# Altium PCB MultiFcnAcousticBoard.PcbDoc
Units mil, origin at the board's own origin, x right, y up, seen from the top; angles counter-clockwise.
Board outline 6000 x 4000 mil, 2 copper layers (Top Layer, Bottom Layer); 88 components, 62 nets, 279 pads, 39 vias.
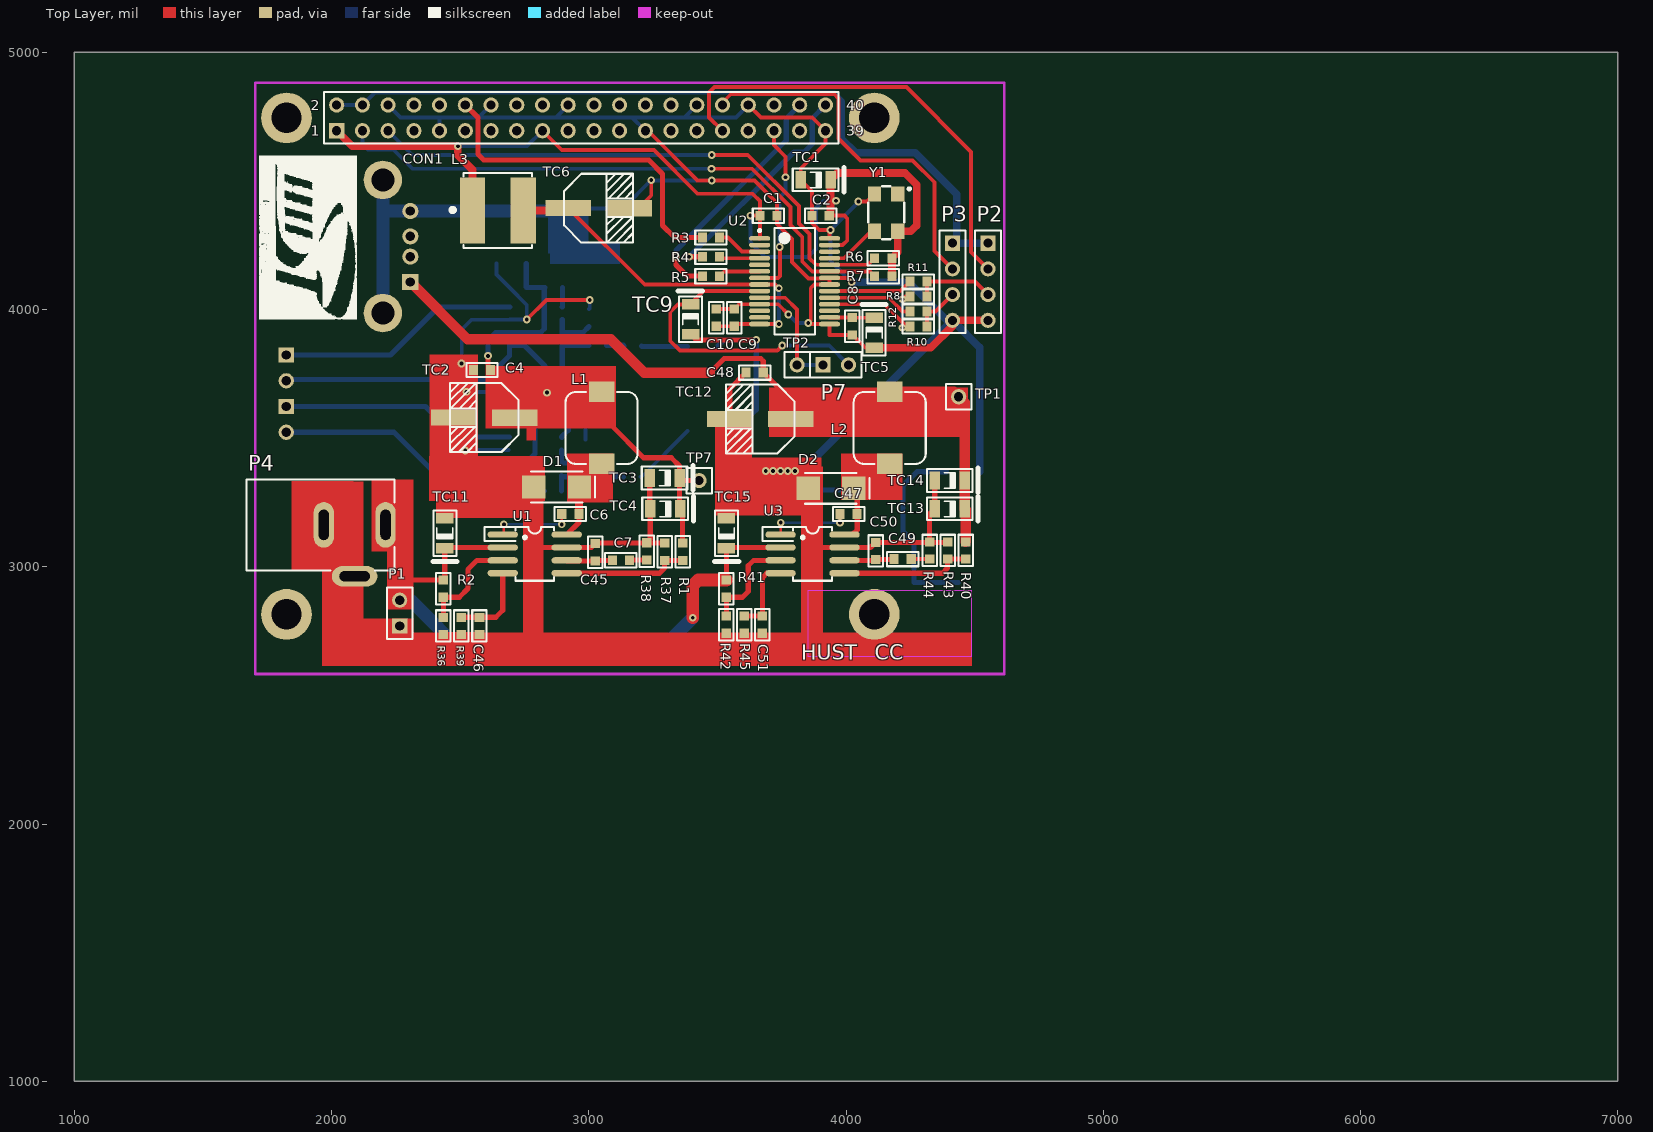
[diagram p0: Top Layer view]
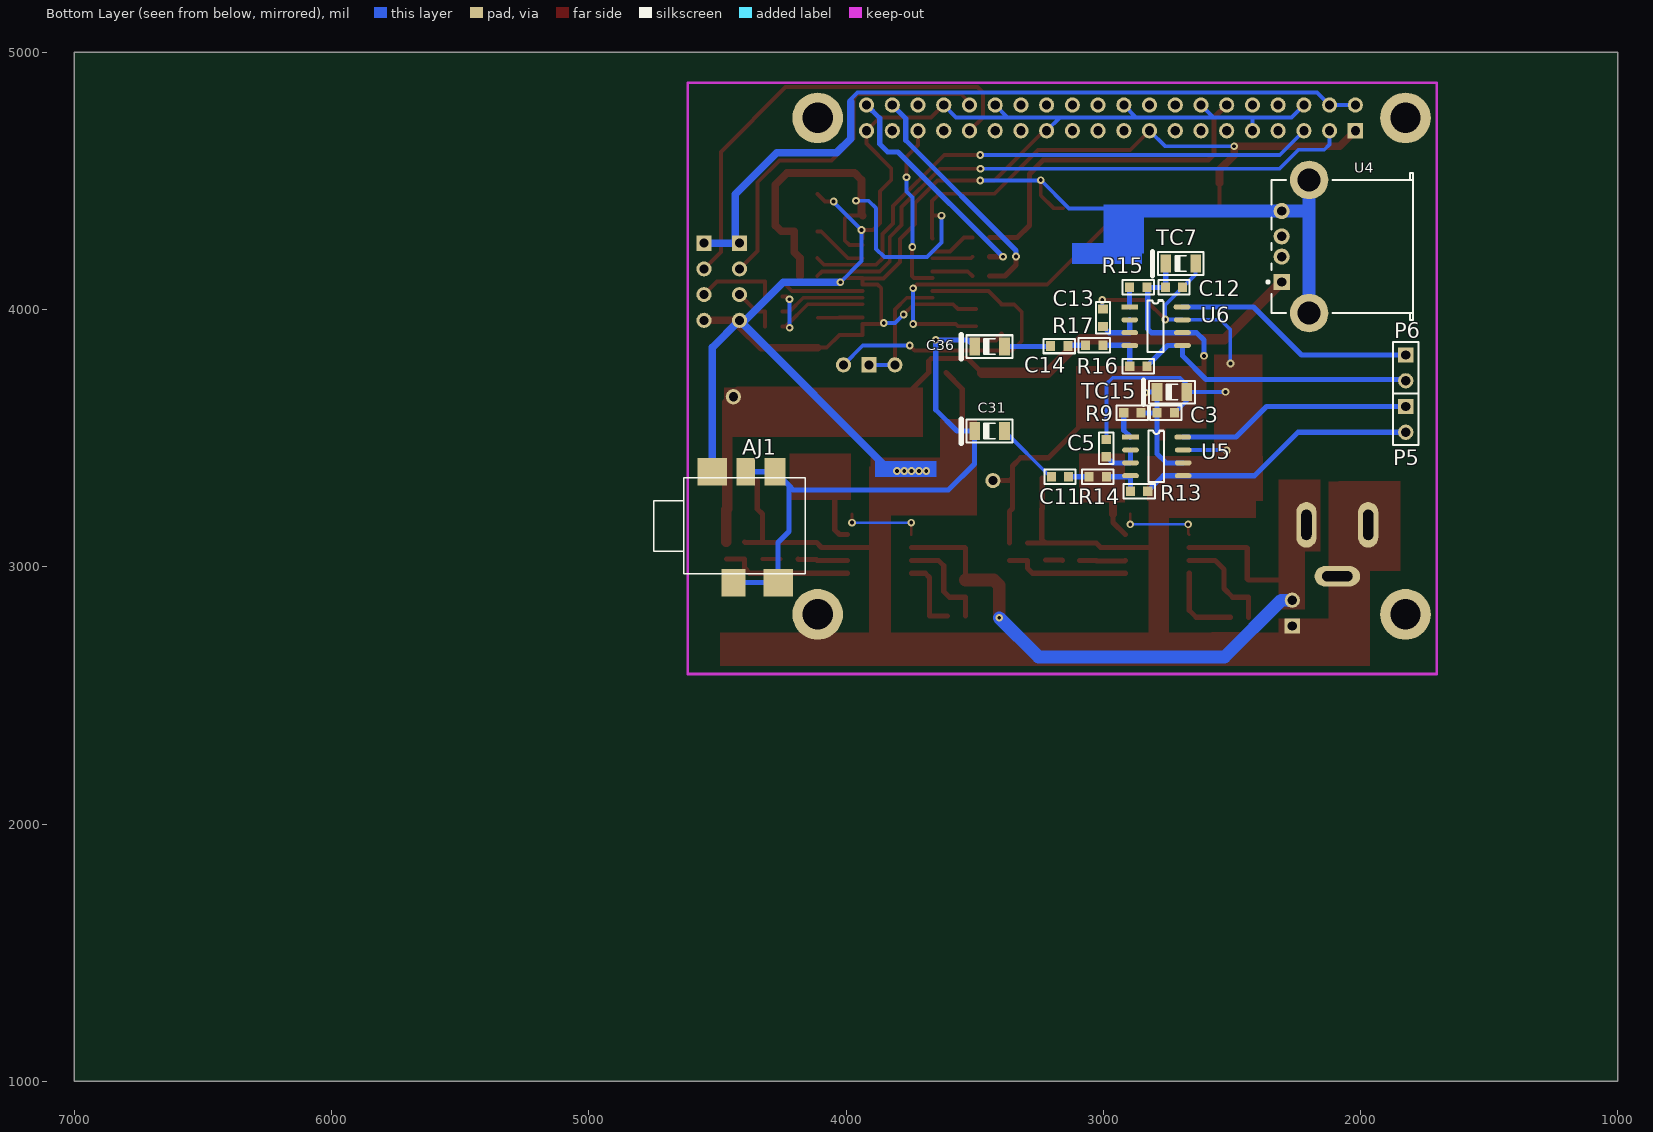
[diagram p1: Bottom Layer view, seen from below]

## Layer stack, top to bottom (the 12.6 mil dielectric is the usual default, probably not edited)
Top Solder: solder mask 0.4, Solder Resist, Dk 3.5
Top Layer: signal copper 1.4
Dielectric 1: dielectric 12.6, FR-4, Dk 4.8
Bottom Layer: signal copper 1.4
Bottom Solder: solder mask 0.4, Solder Resist, Dk 3.5

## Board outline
1000,1000 7000,1000 7000,5000 1000,5000

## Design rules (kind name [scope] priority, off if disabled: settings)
Clearance [All] p1: gap=5
PolygonConnect [All] p1: connectstyle=Relief reliefconductorwidth=10 reliefentries=4 polygonreliefangle="90 Angle" airgapwidth=10
RoutingVias [All] p1: holewidth=28 width=50 viastyle="Through Hole" minholewidth=5 minwidth=10 maxholewidth=50 maxwidth=100
SolderMaskExpansion [All] p1: expansion=4
Width [All] p1: maxlimit=100 minlimit=10 preferedwidth=30
30 further rules are at their usual default settings.

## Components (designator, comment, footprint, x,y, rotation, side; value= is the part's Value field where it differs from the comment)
AJ1 "AUDIOJACK" AUDIOJACK_SJ1-3515-SMT-TR-BE 4392,3154 r180 bottom
C1 "0.1uF/0603" C0603 3698.46,4365 r180 top
C2 "0.1uF/0603" C0603 3901.54,4365 r0 top
C3 "0.1uF/0603" C0603 2757,3598 r0 bottom
C4 "0.1uF/0603" C0603 2585,3765 r0 top
C5 "1uF/0603" C0603 2988,3461 r270 bottom
C6 "0.1uF/0603" C0603 2928.46,3205 r0 top
C7 "180pF/0603" C0603 3125,3025 r180 top
C8 "0.1uF/0603" C0603 4025,3935 r90 top
C9 "0.1uF/0603" C0603 3565,3968.46 r270 top
C10 "0.1uF/0603" C0603 3495,3968.46 r270 top
C11 "0.39uF/0603" C0603 3168,3350 r0 bottom
C12 "0.1uF/0603" C0603 2725,4086 r0 bottom
C13 "1uF/0603" C0603 3001,3968 r270 bottom
C14 "0.39uF/0603" C0603 3171,3858 r0 bottom
C31 "1uF/1206" TAN_A 3442,3528 r0 bottom
C36 "1uF/1206" TAN_A 3442,3856 r0 bottom
C45 "12pF/0603" C0603 3025,3056.54 r270 top
C46 "0.015uF/0603" C0603 2575,2770 r90 top
C47 "0.1uF/0603" C0603 4010,3205 r0 top
C48 "0.1uF/0603" C0603 3645,3755 r0 top
C49 "270pF/0603" C0603 4220,3030 r180 top
C50 "12pF/0603" C0603 4115,3061.54 r270 top
C51 "0.015uF/0603" C0603 3675,2775 r90 top
CON1 "RPI_40PIN_CON" HDR2X20 2020,4695 r0 top
D1 "B320A-SMA" DIODE-SMA 2875,3310 r0 top
D2 "B320A-SMA" DIODE-SMA 3941.42,3305 r0 top
L1 "3.3uH/1264EY-100M=P3" L-SMD-7 3050,3540 r90 top
L2 "3.3uH/1264EY-100M=P3" L-SMD-7 4170,3540 r90 top
L3 "10uH/1264EY-100M=P3" INDUCTOR 2548.15,4385 r0 top
P1 "Header 2" HDR1X2 2265,2770 r90 top
P2 "Header 4" HDR1X4 4552,4258 r270 top
P3 "Header 4" HDR1X4 4414,4258 r270 top
P4 "Header 3" DC-005 2245,3163 r180 top
P5 "Header 2" HDR1X2 1824,3623 r270 bottom
P6 "Header 2" HDR1X2 1824,3823 r270 bottom
P7 "Header 2" HDR1X2 3910,3785 r0 top
R1 "28.2K/0603" R0603 3365,3058.46 r90 top
R2 "220K/0603" R0603 2435,2915 r270 top
R3 "27 ohm/0603" R0603 3475,4280 r180 top
R4 "1K/0603" R0603 3475,4205 r180 top
R5 "27 ohm/0603" R0603 3475,4130 r180 top
R6 "1K/0603" R0603 4145,4200 r0 top
R7 "1K/0603" R0603 4145,4130 r0 top
R8 "0/0603" R0603 4281.54,4050.67 r0 top
R9 "10K/0603" R0603 2887,3598 r0 bottom
R10 "0/0603" R0603 4281.54,3934 r180 top
R11 "0/0603" R0603 4281.54,4109 r0 top
R12 "0/0603" R0603 4281.54,3992.33 r180 top
R13 "20K/0603" R0603 2860.54,3294 r180 bottom
R14 "20K/0603" R0603 3021.46,3350 r0 bottom
R15 "10K/0603" R0603 2864,4086 r0 bottom
R16 "20K/0603" R0603 2863.54,3780 r180 bottom
R17 "20K/0603" R0603 3035,3861 r0 bottom
R36 "20K/0603" R0603 2435,2770 r90 top
R37 "2K/0603" R0603 3295,3058.46 r270 top
R38 "68.1K/0603" R0603 3225,3060 r270 top
R39 "1M/0603" R0603 2505,2770 r90 top
R40 "10.6K/0603" R0603 4465,3063.46 r90 top
R41 "220K/0603" R0603 3535,2915 r270 top
R42 "20K/0603" R0603 3535,2775 r90 top
R43 "2K/0603" R0603 4395,3063.46 r270 top
R44 "44.2K/0603" R0603 4325,3063.46 r270 top
R45 "1M/0603" R0603 3605,2775 r90 top
TC1 "10uF/TAN/1206" TAN_A 3882,4504 r0 top
TC2 "1000uF" TAN_CAP 2712,3579 r180 top
TC3 "47uF" TAN_A 3295,3345 r0 top
TC4 "47uF" TAN_A 3296.93,3225 r0 top
TC5 "10uF/TAN/1206" TAN_A 4110,3910 r90 top
TC6 "10uF/TAN/1206" TAN_CAP 2920,4395 r0 top
TC7 "47uF" TAN_A 2698.93,4179 r0 bottom
TC9 "47uF" TAN_A 3396,3962 r90 top
TC11 "10uF" TAN_A 2440,3130 r270 top
TC12 "1000uF" TAN_CAP 3785,3574 r180 top
TC13 "47uF" TAN_A 4403.07,3225 r0 top
TC14 "47uF" TAN_A 4403.07,3335 r0 top
TC15 "47uF" TAN_A 2732.93,3679 r0 bottom
TC15 "10uF" TAN_A 3535,3130 r270 top
TP1 "VCC_5" TP 4440,3660 r0 top
TP2 "RPOUT" TP 3811.98,3784.16 r0 top
TP7 "VCC_12" TP 3431,3334 r0 top
U1 "TPS54432" SOIC-8 2790,3050 r0 top
U2 "WM8731SEDS/RV" SSOP-28 3800,4110 r0 top
U3 "TPS54432" SOIC-8 3870,3050 r0 top
U4 "USB" USB_A1 1795,4245 r180 bottom
U5 "8002A" SOP8 2864,3504 r180 bottom
U6 "8002A" SOP8 2867,4010 r180 bottom
Y1 "XATLS" 5032 4161,4379 r90 top

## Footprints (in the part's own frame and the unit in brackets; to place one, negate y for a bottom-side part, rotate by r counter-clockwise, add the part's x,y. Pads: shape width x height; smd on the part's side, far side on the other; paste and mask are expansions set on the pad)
5032 [mm]
  rect 1.5x1.3 smd: 1(1.778,-1.016) 2(1.778,1.27) 3(-1.905,1.27) 4(-1.905,-1.016)
  silkscreen extent -2.67,-2.29 2.54,1.91
AUDIOJACK_SJ1-3515-SMT-TR-BE [mm]
  rect 2.9x2.7 smd: 1(-3.25,5.475) 2(3.25,-5.475)
  rect 2.1x2.7 smd: 3(2.95,5.475)
  rect 2.4x2.7 smd: 10(-1.15,-5.475)
  rect 1.8x2.7 smd: 11(0.05,5.475)
  silkscreen extent -9.05,-4.62 5.95,4.87
C0603 [mm]
  rect 0.9x0.95 smd: 1(0.85,0) 2(-0.85,0)
  silkscreen extent -1.55,-0.71 1.55,0.71, body extent -0.85,-0.45 0.85,0.45, height 0.45
DC-005 [mm] "DC母座5.5mm"
  oval 2x4.5 hole 1 slot 3 at 90 deg: 1(0.889,0) 2(6.985,0)
  oval 4.5x2 hole 1 slot 3 at 0 deg: 3(3.937,5.08)
  silkscreen extent 0,-4.5 14.6,4.5, body extent 0,-4.44 14.6,4.45, height 11
DIODE-SMA [mm] "贴片二极管"
  rect 2.3x2.3 smd: 1(-2.25,0) 2(2.25,0)
  silkscreen extent -2.54,-1.52 3.81,1.52, body extent -2.92,-1.4 2.92,1.4, height 3
HDR1X2 [mm] "Connector; Header; 2 Position"
  rect 1.5x1.5 hole 0.9: 1(0,0)
  round 1.5 hole 0.9: 2(2.54,0)
  silkscreen extent -1.27,-1.27 3.81,1.27
HDR1X4 [mm] "Connector; Header; 4 Position"
  rect 1.5x1.5 hole 0.9: 1(0,0)
  round 1.5 hole 0.9: 2(2.54,0) 3(5.08,0) 4(7.62,0)
  silkscreen extent -1.27,-1.27 8.89,1.27
HDR2X20 [mm] "Connector; Header; 20x2 Position"
  rect 1.5x1.5 hole 0.9: 1(0,0)
  round 1.5 hole 0.9: 2(0,2.54) 3(2.54,0) 4(2.54,2.54) 5(5.08,0) 6(5.08,2.54) 7(7.62,0) 8(7.62,2.54) 9(10.16,0) 10(10.16,2.54) 11(12.7,0) 12(12.7,2.54) 13(15.24,0) 14(15.24,2.54) 15(17.78,0) 16(17.78,2.54) 17(20.32,0) 18(20.32,2.54) 19(22.86,0) 20(22.86,2.54) 21(25.4,0) 22(25.4,2.54) 23(27.94,0) 24(27.94,2.54) 25(30.48,0) 26(30.48,2.54) 27(33.02,0) 28(33.02,2.54) 29(35.56,0) 30(35.56,2.54) 31(38.1,0) 32(38.1,2.54) 33(40.64,0) 34(40.64,2.54) 35(43.18,0) 36(43.18,2.54) 37(45.72,0) 38(45.72,2.54) 39(48.26,0) 40(48.26,2.54)
  silkscreen extent -1.27,-1.27 49.53,3.81
INDUCTOR [mm]
  rect 2.5x6.5 smd: 1(0,0) 2(5,0)
  silkscreen extent -2.11,-3.7 5.88,3.7
L-SMD-7 [mm] "贴片电感7*7"
  rect 2x2.5 smd: 1(-3.556,0) 2(3.556,0)
  silkscreen extent -3.56,-3.56 3.56,3.56, body extent -3.56,-3.56 3.56,3.56, height 4
R0603 [mm]
  rect 0.9x0.95 smd: 1(0.85,0) 2(-0.85,0)
  silkscreen extent -1.55,-0.71 1.55,0.71, body extent -0.85,-0.45 0.85,0.45, height 0.45
SOIC-8 [mil] "SOIC, 8-Leads, Body 5.0x4.0mm (max), Pitch 1.27mm, IPC Medium Density"
  oval 118.11x24 smd: 1(-124.32,75) 2(-124.32,25) 3(-124.32,-25) 4(-124.32,-75) 5(124.32,-75) 6(124.32,-25) 7(124.32,25) 8(124.32,75)
  silkscreen extent -195,-104 75,104, body extent -75,-99 75,101, height 69
SOP8 [mm]
  rect 1.657x0.5 smd: 1(-0.762,0)
  oval 1.657x0.5 smd: 2(-0.762,-1.27) 3(-0.762,-2.54) 4(-0.762,-3.81) 5(4.445,-3.81) 6(4.445,-2.54) 7(4.445,-1.27) 8(4.394,0)
  silkscreen extent 1.02,-4.44 2.57,0.63
SSOP-28 [mm] "FT232"
  oval 2.1x0.45 smd: 1(-3.45,4.225) 2(-3.45,3.575) 3(-3.45,2.925) 4(-3.45,2.275) 5(-3.45,1.625) 6(-3.45,0.975) 7(-3.45,0.325) 8(-3.45,-0.325) 9(-3.45,-0.975) 10(-3.45,-1.625) 11(-3.45,-2.275) 12(-3.45,-2.925) 13(-3.45,-3.575) 14(-3.45,-4.225) 15(3.45,-4.225) 16(3.45,-3.575) 17(3.45,-2.925) 18(3.45,-2.275) 19(3.45,-1.625) 20(3.45,-0.975) 21(3.45,-0.325) 22(3.45,0.325) 23(3.45,0.975) 24(3.45,1.625) 25(3.45,2.275) 26(3.45,2.925) 27(3.45,3.575) 28(3.45,4.225)
  silkscreen extent -3.57,-5.25 2,5.25, body extent -2.8,-5.25 2.8,5.25, height 2
TAN_A [mm]
  rect 1.05x1.75 smd: 1(1.475,0) 2(-1.475,0)
  silkscreen extent -2.26,-1.17 2.79,1.22, body extent -1.6,-0.85 1.6,0.85, height 0.55
TAN_CAP [mm]
  rect 4.5x1.6 smd: 1(0,0) 2(6.02,-0.025)
  silkscreen extent -0.4,-3.43 6.4,3.37
TP [mm]
  round 1.5 hole 0.9: 1(-0.05,0.021)
  silkscreen extent -1.32,-1.25 1.22,1.29
USB_A1 [mm]
  rect 1.6x1.6 hole 0.92: 1(-12.99,-3.5)
  round 1.6 hole 0.92: 2(-12.99,-1) 3(-12.99,1) 4(-12.99,3.5)
  round 3.8 hole 2.3: 5(-10.28,6.57) 6(-10.28,-6.57)
  silkscreen extent -14.47,-7.25 0,7.25

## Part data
C1 C2 C3 C4 C5 C6 C7 C8 C9 C10 C11 C12 C13 C14 C31 C36 C45 C46 C47 C48 C49 C50 C51: library part C
D1 D2: library part "Diode 1N4003", "1 Amp General Purpose Rectifier"
L1 L2 L3: library part L
P1 P5 P6 P7: "Header, 2-Pin"
P2 P3: "Header, 4-Pin"
P4: "Header, 3-Pin"
R1 R2 R3 R4 R5 R6 R7 R8 R9 R10 R11 R12 R13 R14 R15 R16 R17 R36 R37 R38 R39 R40 R41 R42 R43 R44 R45: library part RES
TC1 TC2 TC3 TC4 TC5 TC6 TC7 TC9 TC11 TC12 TC13 TC14 TC15 TC15: library part TAN_C
TP1 TP2 TP7: library part Testpoint
U1 U3: library part TPS54332
U2: library part XWM8731EDS
Y1: "贴片有源晶振"

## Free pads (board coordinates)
  round 196.85 hole 118.11: 0(4110,2815) 0(4110,4745) 1(1825,4745) 2(1825,2815)

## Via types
v1: diameter 30, hole 15, Top Layer to Bottom Layer, 39 vias

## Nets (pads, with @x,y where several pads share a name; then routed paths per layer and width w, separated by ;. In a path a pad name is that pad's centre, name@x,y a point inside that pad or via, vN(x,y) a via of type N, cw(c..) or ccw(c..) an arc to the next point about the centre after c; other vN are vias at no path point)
3V3: C1.1 C2.1 CON1.1 CON1.17 L3.1 R6.1 R7.1 TC1.1 U2.1 U2.27 Y1.4 | length 4095.3
  Top Layer w15: L3.1 L3.1@2548.15,4492 ; CON1.17 2895,4620 3253,4620 3423,4450 3637,4450 3665,4422 C1.1 ; v1(3629,4365) C1.1 ; U2.1 3665,4277.17 C1.1 ; C2.1 3994,4365 4005,4354 4005,4269 3986.75,4250.75 U2.27 ; 3940.07,4423 v1(3961,4423)
  Top Layer w30: CON1.1 2080,4635 v1(2491,4635) 2491,4600 2548.15,4542.85 L3.1@2548.15,4492 ; C2.1 3940.07,4370.07 3940.07,4423 TC1.1 3967.07,4531 4229,4531 4275,4485 4275,4327 4252,4304 Y1.4 4201,4222.54 R6.1 R7.1
  Bottom Layer w15: v1(2491,4635) 2760,4635 CON1.17 ; v1(3629,4365) 3629,4260 3685,4204 3851,4204 3883,4236 3883,4394 3912,4423 v1(3961,4423)
5V: CON1.2 CON1.4 P2.1 P3.1 | length 3018.6
  Bottom Layer w15: CON1.2 CON1.4 2169,4844 3955,4844 3982,4817 3982,4808
  Bottom Layer w30: 3982,4808 3982,4664 4037,4609 4269,4609 4430,4448 4430,4274 P3.1 P2.1
ACD_MISO: CON1.38 R5.1 | length 941.6
  Top Layer w20: v1(3339,4206) 3339,4173 3382,4130 R5.1
  Bottom Layer w20: v1(3339,4206) 3339,4229 3768,4658 3768,4743 CON1.38
ACD_MOSI: CON1.40 R4.1 | length 884.5
  Top Layer w20: v1(3390,4205) R4.1
  Bottom Layer w20: v1(3390,4205) 3797.5,4612.5 3837.5,4612.5 3869,4644 3869,4744 CON1.40
ACD_SCK: CON1.12 R3.1 | length 1335.2
  Top Layer w20: CON1.12 2569,4746 2569,4604 2592,4581 3233,4581 3287,4527 3287,4327 3334,4280 R3.1
ADCLRC: CON1.35 U2.7 | length 676.1
  Top Layer w15: U2.7 3735.8,4122.8 3743.8,4130.8 3743.8,4241.2 v1(3742,4243) ; CON1.35 3720,4639 3765,4594 v1(3765,4514)
  Bottom Layer w15: v1(3742,4243) 3742,4436 3765,4459 v1(3765,4514)
AMP1: C11.1 C31.2 | length 256.2
  Bottom Layer w15: C11.1 3205.93,3350 C31.2
AMP2: C14.1 C36.2 | length 180.3
  Bottom Layer w20: C14.1 3206.46,3856 C36.2
BAT_IN: P1.2 P4.1 R2.2 R41.2 TC11.1 TC15.1@3535,3071.93 U1.2 U3.2 | length 2490.8
  Top Layer w20: P1.2 2265,2941 2272.46,2948.46 R2.2 2440,2953.46 TC11.1 2443.07,3075 U1.2 ; R41.2 3535,3071.93 3538.07,3075 U3.2
  Top Layer w50: v1(3404,2802) 3404,2927 3425.46,2948.46 R41.2
  Bottom Layer w50: P1.2 2308,2870 2529,2649 3251,2649 v1(3404,2802)
CTRL1: CON1.31 P2.2 | length 1783.3
  Top Layer w15: CON1.31 3468,4747 3468,4843.5 3489,4864.5 4234.5,4864.5 4486,4613 4486,4224 P2.2
CTRL2: CON1.32 P3.2 | length 1446.3
  Top Layer w15: CON1.32 3520,4805 3552.03,4837.03 3954.97,4837.03 3971,4821 3971,4665 4056,4580 4259,4580 4344,4495 4344,4228 P3.2
GND: AJ1.1 C1.2 C2.2 C3.2 C4.2 C5.2 C8.2 C9.2 C10.2 C12.2 C13.2 C45.2 C46.2 C48.2 C50.2 C51.2 CON1.6 CON1.9 CON1.14 CON1.20 CON1.25 CON1.30 CON1.34 CON1.39 D1.1 D2.1 P1.1 P2.4 P3.4 P4.2 P4.3 R36.2 R37.2 R38.2 R39.2 R42.2 R43.2 R44.2 R45.2 TC1.2 TC2.2 TC3.2 TC4.2 TC5.2 TC6.2 TC7.2 TC11.2 TC12.2 TC13.2 TC14.2 TC15.2 U1.7 U2.11 U2.15 U2.21 U2.22 U2.28 U3.7 U4.4 U4.5 U4.6 U5.7 U6.7 Y1.2 | length 13709.3
  Top Layer w15: v1(2759,3961) 2835,4037 v1(3004,4037) ; TC6.2 3193,4394 3243,4444 v1(3243,4503) ; CON1.25 3230,4695 3423,4502 v1(3478,4502) 3644,4502 3731.93,4414.07 C1.2 3731.93,4332.07 3790,4274 3790,4185 3854,4121 3934.03,4121 U2.22 ; C10.2 C9.2 3583.5,4020.43 U2.11 3736.57,4020.43 v1(3776,3981) ; CON1.34 3669,4746 3869,4746 CON1.39 3920,4645 3823.93,4548.93 TC1.2 3868.07,4459.86 C2.2 3868.07,4336.93 3896,4309 v1(3940,4309) 3935.83,4304.83 U2.28 ; v1(4022,4106) 4005.2,4122.8 U2.22 ; v1(4048,4420) 4082,4420 Y1.2 ; TC5.2 4074.61,3851.93 C8.2 3935.83,3901.54 U2.15 3857.34,3943.66 v1(3853,3948) 3863,3958 3863,4083 3877.2,4097.2 U2.21 U2.22
  Top Layer w20: 2265,2699 P1.1 ; R36.2 R39.2 C46.2 ; 2806,3076 2807,3075 U1.7 3010,3075 C45.2 3026.93,3091.93 R37.2 ; R38.2 3238.86,3107.32 TC4.2 3236.93,3226.93 TC3.2 ; TC12.2 3548,3691.46 C48.2 ; 3865,3085 3875,3085 3885,3075 U3.7 4095,3075 C50.2 4393.07,3095 R43.2 ; R44.2 4325,3205 TC13.2 TC14.2
  Top Layer w30: v1@3681,3374 3686,3374 v1(3688,3372) 3714,3372 3715,3371 3742,3371 3746,3367 3771,3367 3772,3368 v1@3802,3368 ; TC5.2 4329.93,3851.93 4414,3936 P3.4 P2.4
  Bottom Layer w15: CON1.6 2268,4747 2426,4747 ; CON1.9 2420,4741 2426,4747 ; v1(2505,3790) 2506,3791 2506,3923 2543,3960 U6.7 2693,3961 v1(2759,3961) 2759,4018 2691.54,4085.46 C12.2 2640.86,4136.68 TC7.2 ; v1(2520,3452) 2522,3454 U5.7 ; v1(2525,3680) 2526,3679 TC15.2@2674.86,3679 ; CON1.14 2572,4747 ; C3.2 2674.86,3646.68 TC15.2@2674.86,3679 ; CON1.20 2872,4747 ; 2983,4393 3133,4393 v1(3243,4503) ; C5.2 2988,3710 2963,3735 2701,3735 2674.86,3708.86 TC15.2@2674.86,3679 ; C13.2 3004,4004.46 v1(3004,4037) ; CON1.25 3168,4747 ; v1@3244,4502 v1(3478,4502) ; CON1.30 3372,4747 ; CON1.34 3572,4747 3372,4747 ; v1(3776,3981) 3809,3948 v1(3853,3948) ; v1(4022,4106) 3940,4188 v1(3940,4309) 4051,4420 v1(4048,4420) ; 2426,4747 2572,4747 ; 2572,4747 2872,4747 ; 2872,4747 3168,4747 ; 3168,4747 3372,4747
  Bottom Layer w20: 2995,4232 3041,4232
  Bottom Layer w30: v1(3802,3372) 3828,3372 P3.4 ; v1(4022,4106) 4244,4106 4392,3958 P3.4 ; AJ1.1 4519.95,3852.05 P3.4
  Bottom Layer w50: U4.6 2199.72,4366 ; U4.5 2199.72,4366 ; 2892,4368 2877.2,4382.8 U4.4 2216.52,4382.8 2199.72,4366
  other v1: 3716.5,3372 3745,3372 3773.5,3372
I2C_SCL: CON1.5 R6.2 U2.24 | length 2213
  Top Layer w15: v1(3478,4601) 3618,4601 3817,4402 3817,4335 3858,4294 3858,4199 3883.02,4173.98 U2.24 4085.51,4173.98 R6.2
  Bottom Layer w15: CON1.5 2314,4601 v1(3478,4601)
I2C_SDA: CON1.3 R7.2 U2.23 | length 2353.3
  Top Layer w15: v1(3477.5,4547.5) 3634.5,4547.5 3784,4398 3784,4328 3830,4282 3830,4187 3868.61,4148.39 U2.23 4093.15,4148.39 R7.2
  Bottom Layer w15: CON1.3 2120,4642 2141,4621 2241,4621 2314.5,4547.5 v1(3477.5,4547.5)
LLIN: R11.2 U2.20 | length 327.7
  Top Layer w15: U2.20 4210.69,4071.61 R11.2
LPOUT: P7.2 TC9.1 U2.9 | length 1241.4
  Top Layer w15: U2.9 3446.61,4071.61 3396,4021 TC9.1 3346.07,4020.07 3317,3991 3317,3878 3354,3841 3733,3841 v1(3752,3860)
  Bottom Layer w15: v1(3752,3860) 3935,3860 P7.2
MICIN: R8.2 R10.1 U2.18 | length 502.2
  Top Layer w15: U2.18 4148.57,4020.43 v1@4229.5,3939.5 ; v1(4219,3929) 4224,3934 R10.1 ; v1(4220,4040) 4230.67,4050.67 R8.2
  Bottom Layer w15: v1(4219,3929) 4220,3930 v1(4220,4040)
NetAJ1_2: AJ1.2 AJ1.3 AJ1.10 AJ1.11 C31.1 C36.1 TC9.2 | length 2539.6
  Top Layer w20: TC9.2 3417.93,3882 v1(3651,3882)
  Bottom Layer w20: C36.1 3526.07,3882 v1(3651,3882) 3651,3610 3569,3528 C31.1 3500.07,3399.93 3601,3299 4205.31,3299 4221.93,3315.63 ; AJ1.11 AJ1.3 4221.93,3315.63 ; AJ1.10 AJ1.2 4264.05,3094.47 4221.93,3136.58 4221.93,3315.63
NetC5_1: C5.1 U5.2 U5.3 | length 153.7
  Bottom Layer w20: U5.2 U5.3 2964.46,3404 C5.1
NetC6_1: C6.1 D1.2 L1.1 U1.8 | length 205.4
  Top Layer w20: U1.8 2961.93,3172.61 C6.1
  Top Layer w30: C6.1 2961.93,3308.35 D1.2
NetC6_2: C6.2 U1.1 | length 306.8
  Top Layer w10: U1.1 2670,3129.32 v1(2670,3165) ; v1(2895,3165) C6.2
  Bottom Layer w10: v1(2670,3165) v1(2895,3165)
NetC7_1: C7.1 C45.1 U1.6 | length 178.8
  Top Layer w20: U1.6 2916.24,3023.07 C45.1 3026.93,3025 C7.1
NetC7_2: C7.2 R38.1 | length 67.2
  Top Layer w20: C7.2 3160,3026.54 R38.1
NetC8_1: C8.1 TC5.1 U2.16 | length 174.7
  Top Layer w15: U2.16 4024.21,3969.25 C8.1 4025.39,3968.07 TC5.1
NetC9_1: C9.1 C10.1 L3.2 TC6.1 U2.8 U2.14 | length 1514.1
  Top Layer w15: TC6.1@2875,4385 2910,4385 TC6.1 3217.8,4097.2 U2.8 3724.8,4097.2 v1(3739,4083) ; C10.1 C9.1 3573.66,3943.66 U2.14 3664.51,3944 v1(3739,3944)
  Top Layer w30: L3.2 TC6.1@2875,4385
  Bottom Layer w15: v1(3739,3944) v1(3739,4083)
NetC11_2: C11.2 R14.1 | length 79.6
  Bottom Layer w20: R14.1 C11.2
NetC13_1: C13.1 U6.2 U6.3 | length 164.2
  Bottom Layer w20: U6.2 U6.3 2976.46,3910 C13.1
NetC14_2: C14.2 R17.1 | length 70.3
  Bottom Layer w20: R17.1 3134.54,3861 C14.2
NetC46_1: C46.1 R39.1 U1.4 | length 316.3
  Top Layer w20: R39.1 C46.1 2638.46,2803.46 2665.68,2830.68 U1.4
NetC47_1: C47.1 D2.2 L2.1 U3.8 | length 223.9
  Top Layer w20: U3.8 4025,3125 4043.46,3143.46 C47.1 4043.46,3291.54 D2.2
NetC47_2: C47.2 U3.1 | length 310.4
  Top Layer w10: U3.1 3745.68,3170.68 v1(3746.54,3171.54) ; v1(3976.54,3171.54) C47.2
  Bottom Layer w10: v1(3746.54,3171.54) v1(3976.54,3171.54)
NetC49_1: C49.1 C50.1 U3.6 | length 194.3
  Top Layer w10: C50.1@4111.93,3025 C50.1
  Top Layer w20: U3.6 C50.1@4111.93,3025 ; C50.1 4184.61,3028.07 C49.1
NetC49_2: C49.2 R44.1 | length 71.5
  Top Layer w15: C49.2 R44.1
NetC51_1: C51.1 R45.1 U3.4 | length 297.3
  Top Layer w20: R45.1 C51.1 3675,2958 3692,2975 U3.4
NetP2_3: P2.3 R8.1 R11.1 | length 316.5
  Top Layer w15: R8.1 R11.1 4501,4109 P2.3
NetP3_3: P3.3 R10.2 R12.2 | length 184.5
  Top Layer w15: R10.2 R12.2 4348.33,3992.33 P3.3
NetP5_1: P5.1 U5.8 | length 916.3
  Bottom Layer w20: P5.1 2365,3623 2484,3504 U5.8
NetP5_2: P5.2 R13.1 U5.5 | length 1097.9
  Bottom Layer w20: P5.2 2243,3523 2412,3354 U5.5 2767.07,3354 R13.1
NetP6_1: P6.1 U6.8 | length 947.5
  Bottom Layer w20: P6.1 2229,3823 2416,4010 U6.8
NetP6_2: P6.2 R16.1 U6.5 | length 1119.4
  Bottom Layer w20: P6.2 1829,3728 2600,3728 2692,3820 U6.5 2750.07,3860 R16.1
NetR1_2: R1.2 R37.1 U1.5 | length 489
  Top Layer w20: U1.5 3275,2975 3295,2995 R37.1 R1.2
NetR2_1: R2.1 R36.1 U1.3 | length 412.1
  Top Layer w20: R36.1 R2.1 2496.54,2881.54 2530,2915 2530,2990 2565,3025 U1.3
NetR3_2: R3.2 U2.3 | length 178.4
  Top Layer w15: R3.2 3541,4280 3595.84,4225.16 U2.3
NetR4_2: R4.2 U2.4 | length 158
  Top Layer w15: R4.2 3513.9,4199.57 U2.4
NetR5_2: R5.2 U2.6 | length 163.3
  Top Layer w15: R5.2 3526.85,4148.39 U2.6
NetR9_1: R9.1 U5.1 | length 107.8
  Bottom Layer w20: U5.1@2896,3502 U5.1 2920.46,3530.46 R9.1
NetR13_2: R13.2 R14.2 U5.4 | length 155.7
  Bottom Layer w20: R13.2 U5.4 2898,3350 R14.2
NetR15_1: R15.1 U6.1 | length 76.2
  Bottom Layer w20: U6.1 2897.46,4010.46 R15.1
NetR16_2: R16.2 R17.2 U6.4 | length 184.9
  Bottom Layer w20: R16.2 U6.4 2898,3861 R17.2
NetR40_2: R40.2 R43.1 U3.5 | length 514
  Top Layer w20: U3.5 4375,2975 4395,2995 R43.1 R40.2
NetR41_1: R41.1 R42.1 U3.3 | length 401.8
  Top Layer w20: R42.1 R41.1 3597.54,2881.54 3620,2904 3620,3004 3641,3025 U3.3
NetU2_25: U2.25 Y1.3 | length 218.4
  Top Layer w15: U2.25 3991.57,4199.57 4096,4304 Y1.3
RLIN: R12.1 U2.19 | length 334.5
  Top Layer w15: U2.19 4165.98,4046.02 4219.67,3992.33 R12.1
RPOUT: P7.1 TP2.1 U2.10 | length 479.9
  Top Layer w15: U2.10 3763.98,4046.02 3810,4000 TP2.1
  Bottom Layer w15: TP2.1 P7.1
SPL1_L: 
SPL1_R: 
SPL2_L: 
SPL2_R: 
SPL3_L: 
SPL3_R: 
VCC_5V: C48.1 L2.2 R40.1 TC12.1 TC13.1 TC14.1 TP1.1 U4.1 | length 3132.7
  Top Layer w20: 3471,3754 3526,3809 3669,3809 3678.46,3799.54 C48.1 3785,3648.46 TC12.1
  Top Layer w40: U4.1 2528.62,3885 3085,3885 3216,3754 3471,3754 ; TC12.1 4129,3574 4170,3615 L2.2 4418.86,3680 TP1.1 4461.14,3637.72 TC14.1 TC13.1 4465,3221.14 R40.1
VCC_AP5V: C3.1 C4.1 C12.1 L1.2 R1.1 R9.2 R15.2 TC2.1 TC3.1 TC4.1 TC7.1 TC15.1@2791,3679 TP7.1 U5.6 U6.6 | length 1870.5
  Top Layer w20: v1(2608,3820) 2608,3775.46 C4.1 ; 2831,3730 2833,3728 ; 3087,3550 3213,3424 3321,3424 3353.07,3391.93 TC3.1 ; R1.1 3365,3215 TC4.1 3353.07,3226.93 TC3.1 ; TP7.1 3363.23,3334.84 TC3.1
  Bottom Layer w20: v1(2608,3820) 2608,3881 2637,3910 U6.6 2812,3910 2827,3925 R15.2@2827,4086 ; U5.6 2755,3404 2790.46,3439.46 C3.1 ; TC7.1 2757,4087.46 C12.1 R15.2@2827,4086 ; R15.2 R15.2@2827,4086 ; v1(2838,3677) 2836,3679 2791,3679 2791,3598.54 C3.1 ; R9.2 C3.1
pads on no net: CON1.7 CON1.8 CON1.10 CON1.11 CON1.13 CON1.15 CON1.16 CON1.18 CON1.19 CON1.21 CON1.22 CON1.23 CON1.24 CON1.26 CON1.27 CON1.28 CON1.29 CON1.33 CON1.36 CON1.37 U2.2 U2.5 U2.12 U2.13 U2.17 U2.26 U4.2 U4.3 Y1.1

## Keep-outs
Top Layer:
  rectangle net GND: 3852,2652 4489,2907
Keep-Out Layer:
  lines w10: 1704,2583 1704,4882 1718,4882 4615,4882 4615,2583 ; 1707,2583 2194,2583 ; 2172,2583 2201,2583 2257,2583 ; 2232,2583 2913,2583 ; 2935,2583 2913,2583 ; 4174,2583 4613,2583 ; 4179,2583 2913,2583

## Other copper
Top Layer:
  rectangle net BAT_IN: 2216,2834 2319,3151
  rectangle net BAT_IN: 2156,3059 2318,3340
  rectangle net GND: 2094,2726 2319,2798
  rectangle net GND: 1845,2984 2086,3334
  rectangle net GND: 2407,3189 2795,3270
  rectangle net VCC_5V: 3700,3504 4474,3696
  rectangle net VCC_AP5V: 2599,3537 3106,3780
  rectangle net GND: 2000,2615 4490,2745
  rectangle net GND: 1962,2615 2124,3331
  rectangle net GND: 2745,2680 2825,3390
  rectangle net GND: 3825,2680 3910,3390
  rectangle net GND: 2379,3255 2830,3430
  rectangle net GND: 2380,3355 2570,3825
  rectangle net GND: 3490,3260 3905,3425
  rectangle net GND: 3490,3200 3880,3295
  rectangle net GND: 3490,3360 3635,3575
  rectangle net NetC47_1: 3980,3260 4220,3440
  rectangle net NetC6_1: 2915,3250 3095,3440
  rectangle net VCC_AP5V: 2758,3490 2795,3559
Bottom Layer:
  rectangle net GND: 3649,3349 3888,3412
  rectangle net GND: 2849,4177 3122,4259
  rectangle net GND: 2842,4217 2998,4408

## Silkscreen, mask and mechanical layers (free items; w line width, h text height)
Top Overlay:
  drawing of 4822 lines, arcs and shapes, not listed
  text "HUST" at 3827,2620 h100
  text "CC" at 4111,2619 h100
